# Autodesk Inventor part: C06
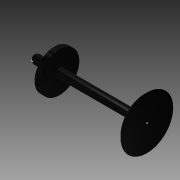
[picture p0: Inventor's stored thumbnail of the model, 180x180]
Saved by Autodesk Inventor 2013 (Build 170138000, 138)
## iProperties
Created: 2006-02
Part Number: C06
Document SubType Name: Modeling
Designer: 40664
Material: Stainless Steel, 440C
Mass: 49.0738 g
Surface Area: 50.6933 cm^2
Volume: 6.3321 cm^3
Density: 7.75 g/cm^3
Author: 40664
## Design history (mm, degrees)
sketch "Sketch1"
  geometry: L1 (-77, 3)-(-65, 3); L2 (-65, 3)-(-65, 14); L3 (-2, 8.5)-(-2, 16.5); L4 (-2, 16.5)-(0, 18.5); L5 (0, 18.5)-(0, 0); L6 (-80, 0)-(0, 0); L7 (-96.746, 0)-(16.124, 0) reference; L8 (0, 22.8)-(0, -7.3) reference; L9 (-61.5, 14)-(-61.5, 3); L10 (-61.5, 3)-(-7.5, 3); L11 (-65, 14)-(-61.5, 14); A1 r 3 centre (-77, 0) between (-77, 3) and (-80, 0); A2 r 5.5 centre (-7.5, 8.5) between (-7.5, 3) and (-2, 8.5)
  constraints: 18 end point, 5 point on line, 4 point on circle, 3 perpendicular, 3 tangent, 2 centre point, 1 collinear, 1 parallel
  dimensions: "d2" = 18.5 distance of L4.end L5.end; "d5" = 2 distance between parallel lines of L3 L5; "d6" = 135 deg angle of L5 L4; "d7" = 8 distance of L3.start L3.end; "d11" = 12 distance of L1.start L1.end; "d12" = 3 radius of A1; "d13" = 80 distance of L6.start L5.end; "d14" = 11 distance of L1.end L2.end; "d15" = 3.5 distance of L2.end L9.start
revolve "Revolution1" sketch "Sketch1" stored, may be unused: angle "d0" = 90 deg
workplane "Work Plane1"
workplane "Work Plane2"
sketch "Sketch2"
  geometry: L1 (-77, -3)-(-77, 3); A1 r 3 centre (-77, 0) between (-77, 3) and (-77, -3) reference; 1 further point
  constraints: 2 end point, 1 vertical
body "Solid1"
